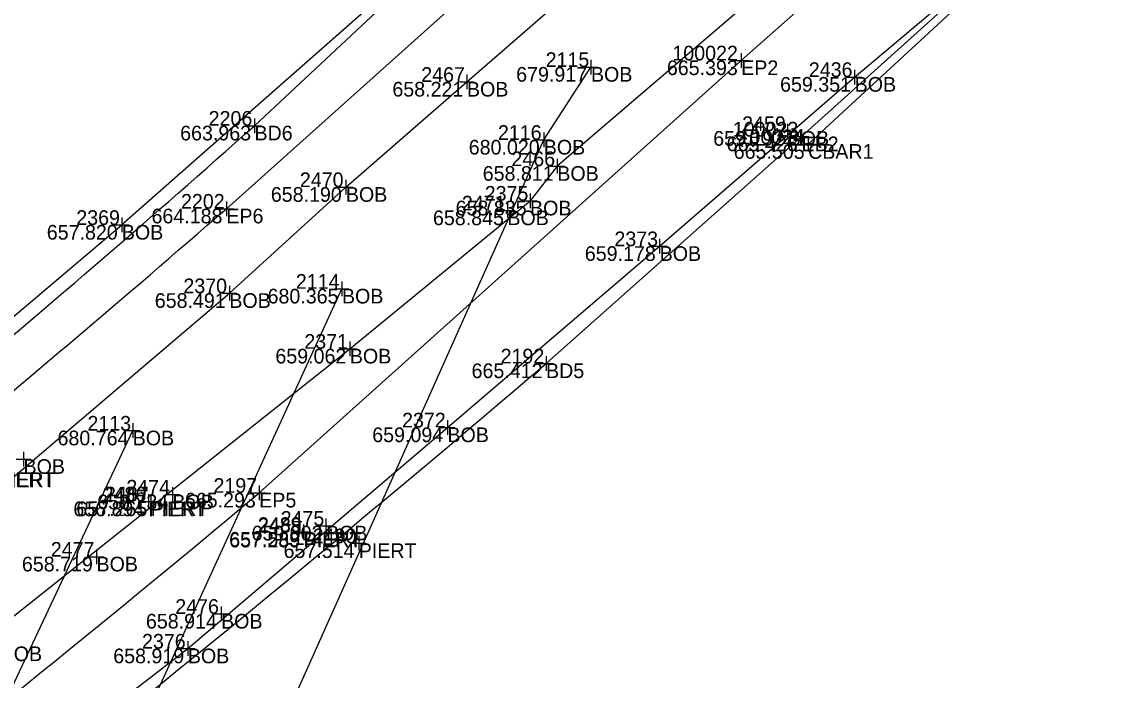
# Model space of a CAD drawing. Extents: x 2197382 to 2204062, y 634117 to 636522.
# Drawn here: x 2202753.9 to 2202828.1, y 635401 to 635445.9 of the extents above; entities that cross this region are included whole.
import ezdxf

# ---------------------------------------------------------------- set-up
doc = ezdxf.new("R2010")
doc.units = 0
for name, color, linetype in [('_CIVIL_CONSTRUCTION', 7, 'Continuous'), ('BR_X_SV_Bottom_of_Beam', 7, 'Continuous'), ('BR_X_SV_Bottom_of_Beam_Text', 7, 'Continuous'), ('BR_X_SV_Deck_Top', 7, 'Continuous'), ('BR_X_SV_Deck_Top_Text', 7, 'Continuous'), ('BR_X_SV_Pier_Cap_Top_Text', 7, 'Continuous'), ('GE_P_Alignment_100_Distances', 7, 'Continuous'), ('GE_X_Alignment', 7, 'Continuous'), ('RD_X_Concrete_Barrier', 7, 'Continuous'), ('SH_Border', 7, 'Continuous'), ('SH_Cut_Line', 7, 'Continuous'), ('SH_Data', 7, 'Continuous')]:
    doc.layers.add(name, color=color, linetype=linetype)

msp = doc.modelspace()

# ---------------------------------------------------------------- linework, layer by layer
at = {"layer": '_CIVIL_CONSTRUCTION'}
for p, q in [((2202802.906, 635443.791), (2202802.906, 635442.791)), ((2202792.169, 635442.844), (2202793.169, 635442.844)), ((2202792.669, 635443.344), (2202792.669, 635442.344)), ((2202792.669, 635442.844), (2202792.669, 635442.844)), ((2202802.406, 635443.291), (2202803.406, 635443.291)), ((2202802.906, 635443.291), (2202802.906, 635443.291)), ((2202784.219, 635442.33), (2202784.219, 635441.33)), ((2202810.139, 635442.162), (2202811.139, 635442.162)), ((2202810.639, 635442.662), (2202810.639, 635441.662)), ((2202810.639, 635442.162), (2202810.639, 635442.162)), ((2202783.719, 635441.83), (2202784.719, 635441.83)), ((2202784.219, 635441.83), (2202784.219, 635441.83)), ((2202769.739, 635439.34), (2202769.739, 635438.34)), ((2202769.239, 635438.84), (2202770.239, 635438.84)), ((2202769.739, 635438.84), (2202769.739, 635438.84)), ((2202789.454, 635438.376), (2202789.454, 635437.376)), ((2202805.573, 635438.476), (2202806.573, 635438.476)), ((2202806.073, 635438.976), (2202806.073, 635437.976)), ((2202806.073, 635438.476), (2202806.073, 635438.476)), ((2202807.016, 635438.602), (2202807.016, 635437.602)), ((2202788.954, 635437.876), (2202789.954, 635437.876)), ((2202789.454, 635437.876), (2202789.454, 635437.876)), ((2202806.516, 635438.102), (2202807.516, 635438.102)), ((2202806.966, 635437.584), (2202807.966, 635437.584)), ((2202807.016, 635438.102), (2202807.016, 635438.102)), ((2202807.466, 635438.084), (2202807.466, 635437.084)), ((2202807.466, 635437.584), (2202807.466, 635437.584)), ((2202789.875, 635436.086), (2202790.875, 635436.086)), ((2202790.375, 635436.586), (2202790.375, 635435.586)), ((2202790.375, 635436.086), (2202790.375, 635436.086)), ((2202775.467, 635434.655), (2202776.467, 635434.655)), ((2202775.967, 635435.155), (2202775.967, 635434.155)), ((2202775.967, 635434.655), (2202775.967, 635434.655)), ((2202788.518, 635434.229), (2202788.518, 635433.229)), ((2202767.323, 635433.185), (2202768.323, 635433.185)), ((2202767.823, 635433.685), (2202767.823, 635432.685)), ((2202767.823, 635433.185), (2202767.823, 635433.185)), ((2202786.973, 635433.561), (2202786.973, 635432.561)), ((2202788.018, 635433.729), (2202789.018, 635433.729)), ((2202788.518, 635433.729), (2202788.518, 635433.729)), ((2202760.7, 635432.577), (2202760.7, 635431.577)), ((2202786.473, 635433.061), (2202787.473, 635433.061)), ((2202786.973, 635433.061), (2202786.973, 635433.061)), ((2202760.2, 635432.077), (2202761.2, 635432.077)), ((2202760.7, 635432.077), (2202760.7, 635432.077)), ((2202797.351, 635431.125), (2202797.351, 635430.125)), ((2202796.851, 635430.625), (2202797.851, 635430.625)), ((2202797.351, 635430.625), (2202797.351, 635430.625)), ((2202768.027, 635427.922), (2202768.027, 635426.922)), ((2202775.701, 635428.223), (2202775.701, 635427.223)), ((2202767.527, 635427.422), (2202768.527, 635427.422)), ((2202768.027, 635427.422), (2202768.027, 635427.422)), ((2202775.201, 635427.723), (2202776.201, 635427.723)), ((2202775.701, 635427.723), (2202775.701, 635427.723)), ((2202775.737, 635423.633), (2202776.737, 635423.633)), ((2202776.237, 635424.133), (2202776.237, 635423.133)), ((2202776.237, 635423.633), (2202776.237, 635423.633)), ((2202789.607, 635423.135), (2202789.607, 635422.135)), ((2202789.107, 635422.635), (2202790.107, 635422.635)), ((2202789.607, 635422.635), (2202789.607, 635422.635)), ((2202761.441, 635418.552), (2202761.441, 635417.552)), ((2202782.387, 635418.269), (2202783.387, 635418.269)), ((2202782.887, 635418.769), (2202782.887, 635417.769)), ((2202782.887, 635418.269), (2202782.887, 635418.269)), ((2202760.941, 635418.052), (2202761.941, 635418.052)), ((2202761.441, 635418.052), (2202761.441, 635418.052)), ((2202753.5, 635416.107), (2202754.5, 635416.107)), ((2202754, 635416.607), (2202754, 635415.607)), ((2202754, 635416.107), (2202754, 635416.107)), ((2202764.147, 635414.193), (2202764.147, 635413.193)), ((2202769.561, 635413.813), (2202770.561, 635413.813)), ((2202770.061, 635414.313), (2202770.061, 635413.313)), ((2202770.061, 635413.813), (2202770.061, 635413.813)), ((2202762.019, 635413.215), (2202763.019, 635413.215)), ((2202762.169, 635413.224), (2202763.169, 635413.224)), ((2202762.519, 635413.715), (2202762.519, 635412.715)), ((2202762.519, 635413.215), (2202762.519, 635413.215)), ((2202762.669, 635413.724), (2202762.669, 635412.724)), ((2202762.669, 635413.224), (2202762.669, 635413.224)), ((2202763.647, 635413.693), (2202764.647, 635413.693)), ((2202764.147, 635413.693), (2202764.147, 635413.693)), ((2202773.076, 635411.645), (2202773.076, 635410.645)), ((2202773.101, 635411.595), (2202773.101, 635410.595)), ((2202774.113, 635411.569), (2202775.113, 635411.569)), ((2202774.613, 635412.069), (2202774.613, 635411.069)), ((2202774.613, 635411.569), (2202774.613, 635411.569)), ((2202772.576, 635411.145), (2202773.576, 635411.145)), ((2202772.601, 635411.095), (2202773.601, 635411.095)), ((2202773.076, 635411.145), (2202773.076, 635411.145)), ((2202773.101, 635411.095), (2202773.101, 635411.095)), ((2202776.844, 635410.872), (2202776.844, 635409.872)), ((2202776.344, 635410.372), (2202777.344, 635410.372)), ((2202776.844, 635410.372), (2202776.844, 635410.372)), ((2202758.475, 635409.456), (2202759.475, 635409.456)), ((2202758.975, 635409.956), (2202758.975, 635408.956)), ((2202758.975, 635409.456), (2202758.975, 635409.456)), ((2202767.464, 635406.063), (2202767.464, 635405.063)), ((2202766.964, 635405.563), (2202767.964, 635405.563)), ((2202767.464, 635405.563), (2202767.464, 635405.563)), ((2202765.2, 635403.692), (2202765.2, 635402.692)), ((2202764.7, 635403.192), (2202765.7, 635403.192)), ((2202765.2, 635403.192), (2202765.2, 635403.192))]:
    msp.add_line(p, q, dxfattribs=at)
at = {"layer": 'BR_X_SV_Bottom_of_Beam'}
for p, q in [((2202789.454, 635437.876), (2202792.669, 635442.844)), ((2202772.072, 635399.002), (2202789.454, 635437.876)), ((2202758.945, 635391.176), (2202775.701, 635427.723)), ((2202745.383, 635383.923), (2202761.441, 635418.052))]:
    msp.add_line(p, q, dxfattribs=at)
for points in [[(2202799.593, 635465.947), (2202791.545, 635459.107), (2202782.041, 635450.982), (2202777.711, 635447.061), (2202760.7, 635432.077)], [(2202768.027, 635427.422), (2202775.967, 635434.655), (2202784.219, 635441.83), (2202796.455, 635452.491), (2202804.428, 635459.062), (2202811.432, 635465.056)], [(2202821.428, 635462.569), (2202813.764, 635456.102), (2202803.94, 635447.733), (2202790.375, 635436.086), (2202788.518, 635433.729)], [(2202550.738, 635261.3), (2202572.992, 635273.891), (2202594.556, 635285.879), (2202604.099, 635291.315), (2202615.232, 635297.565), (2202632.636, 635308.407), (2202649.916, 635319.32), (2202686.545, 635342.9), (2202715.55, 635365.054), (2202734.551, 635379.543), (2202765.2, 635403.192), (2202782.887, 635418.269), (2202797.351, 635430.625), (2202810.639, 635442.162), (2202822.488, 635452.15)], [(2202692.151, 635358.452), (2202706.563, 635369.157), (2202730.439, 635387.213), (2202776.237, 635423.633), (2202788.518, 635433.729)], [(2202513.324, 635270.745), (2202518.461, 635273.222), (2202532.26, 635280.283), (2202548.237, 635288.645), (2202560.651, 635295.117), (2202588.283, 635310.399), (2202608.693, 635322.992), (2202620.515, 635330.213), (2202626.072, 635333.707), (2202636.254, 635340.133), (2202656.933, 635353.888), (2202662.455, 635358.969), (2202720.902, 635399.769), (2202735.154, 635410.438), (2202760.7, 635432.077)], [(2202624.848, 635323.108), (2202626.632, 635325.163), (2202640.898, 635333.252), (2202660.713, 635346.321), (2202681.445, 635361.418), (2202700.993, 635375.17), (2202725.622, 635393.015), (2202741.163, 635404.571), (2202768.027, 635427.422)]]:
    msp.add_lwpolyline(points, dxfattribs=at)
at = {"layer": 'BR_X_SV_Deck_Top'}
for p, q in [((2202769.739, 635438.84), (2202791.176, 635458.867)), ((2202789.607, 635422.635), (2202807.016, 635438.102))]:
    msp.add_line(p, q, dxfattribs=at)
for points in [[(2202430.051, 635233.588), (2202439.74, 635238.507), (2202466.339, 635247.691), (2202507.168, 635268.028), (2202543.723, 635286.397), (2202574.877, 635303.715), (2202604.911, 635320.157), (2202634.127, 635339.4), (2202663.018, 635358.594), (2202692.445, 635376.507), (2202729.246, 635404.451), (2202755.806, 635426.417), (2202769.739, 635438.84)], [(2202458.051, 635216.681), (2202477.116, 635219.979), (2202511.723, 635243.78), (2202554.955, 635262.299), (2202588.014, 635280.674), (2202608.342, 635292.387), (2202640.833, 635312.137), (2202668.147, 635329.948), (2202698.573, 635351.315), (2202722.135, 635368.649), (2202754.604, 635393.426), (2202777.494, 635412.293), (2202789.607, 635422.635)]]:
    msp.add_open_spline(points, degree=3, dxfattribs=at)
at = {"layer": 'GE_P_Alignment_100_Distances'}
for p, q in [((2202767.823, 635433.185), (2202793.579, 635456.25)), ((2202770.061, 635413.813), (2202802.906, 635443.291))]:
    msp.add_line(p, q, dxfattribs=at)
msp.add_lwpolyline([(2202838.828, 635477.544), (2202824.168, 635462.1), (2202802.906, 635443.291)], dxfattribs=at)
for points in [[(2202483.163, 635252.761), (2202495.402, 635258.227), (2202515.209, 635267.824), (2202539.505, 635280.183), (2202556.272, 635289.074), (2202570.794, 635297.089), (2202585.76, 635305.335), (2202607.83, 635319.01), (2202630.778, 635332.646), (2202656.431, 635348.815), (2202675.69, 635362.468), (2202698.981, 635379.185), (2202729.904, 635401.353), (2202753.674, 635420.874), (2202767.823, 635433.185)], [(2202457.668, 635223.282), (2202466.48, 635226.872), (2202500.455, 635242.355), (2202539.476, 635261.183), (2202573.06, 635279.52), (2202585.609, 635286.631), (2202599.84, 635294.842), (2202617.618, 635305.231), (2202642.294, 635320.395), (2202667.372, 635336.77), (2202691.723, 635353.633), (2202713.413, 635369.403), (2202739.641, 635388.973), (2202758.657, 635404.276), (2202770.061, 635413.813)]]:
    msp.add_open_spline(points, degree=3, dxfattribs=at)
at = {"layer": 'GE_X_Alignment'}
msp.add_lwpolyline([(2202845.854, 635473.172), (2202828.699, 635457.658), (2202807.016, 635438.102)], dxfattribs=at)
at = {"layer": 'RD_X_Concrete_Barrier'}
msp.add_lwpolyline([(2202849.035, 635475.414), (2202828.969, 635457.445), (2202807.466, 635437.584)], dxfattribs=at)

# ---------------------------------------------------------------- texts
at = {"layer": 'BR_X_SV_Bottom_of_Beam_Text'}
for s, p in [('2115', (2202789.58, 635442.844)), ('2467', (2202781.104, 635441.83)), ('679.917', (2202787.573, 635441.844)), ('BOB', (2202792.669, 635441.844)), ('2436', (2202807.516, 635442.162)), ('659.351', (2202805.557, 635441.162)), ('BOB', (2202810.639, 635441.162)), ('658.221', (2202779.137, 635440.83)), ('BOB', (2202784.219, 635440.83)), ('2459', (2202802.971, 635438.476)), ('2116', (2202786.331, 635437.876)), ('659.192', (2202801, 635437.476)), ('BOB', (2202806.073, 635437.476)), ('680.020', (2202784.34, 635436.876)), ('BOB', (2202789.454, 635436.876)), ('2466', (2202787.252, 635436.086)), ('658.811', (2202785.293, 635435.086)), ('BOB', (2202790.375, 635435.086)), ('2470', (2202772.835, 635434.655)), ('658.190', (2202770.853, 635433.655)), ('BOB', (2202775.967, 635433.655)), ('2375', (2202785.429, 635433.729)), ('2471', (2202783.873, 635433.061)), ('2369', (2202757.598, 635432.077)), ('658.845', (2202781.903, 635432.061)), ('658.835', (2202783.448, 635432.729)), ('BOB', (2202786.973, 635432.061)), ('BOB', (2202788.518, 635432.729)), ('657.820', (2202755.586, 635431.077)), ('BOB', (2202760.7, 635431.077)), ('2373', (2202794.268, 635430.625)), ('659.178', (2202792.251, 635429.625)), ('BOB', (2202797.351, 635429.625)), ('2114', (2202772.56, 635427.723)), ('2370', (2202764.895, 635427.422)), ('658.491', (2202762.945, 635426.422)), ('BOB', (2202768.027, 635426.422)), ('680.365', (2202770.631, 635426.723)), ('BOB', (2202775.701, 635426.723)), ('2371', (2202773.137, 635423.633)), ('659.062', (2202771.164, 635422.633)), ('BOB', (2202776.237, 635422.633)), ('2113', (2202758.358, 635418.052)), ('2372', (2202779.795, 635418.269)), ('659.094', (2202777.765, 635417.269)), ('BOB', (2202782.887, 635417.269)), ('680.764', (2202756.319, 635417.052)), ('BOB', (2202761.441, 635417.052)), ('BOB', (2202754, 635415.107)), ('2474', (2202761.006, 635413.693)), ('658.734', (2202759.025, 635412.693)), ('BOB', (2202764.147, 635412.693)), ('2475', (2202771.524, 635411.569)), ('659.002', (2202769.54, 635410.569)), ('BOB', (2202774.613, 635410.569)), ('2477', (2202755.86, 635409.456)), ('658.719', (2202753.891, 635408.456)), ('BOB', (2202758.975, 635408.456)), ('2476', (2202764.341, 635405.563)), ('658.914', (2202762.342, 635404.563)), ('BOB', (2202767.464, 635404.563)), ('2376', (2202762.077, 635403.192)), ('BOB', (2202752.443, 635402.339)), ('658.919', (2202760.116, 635402.192)), ('BOB', (2202765.2, 635402.192))]:
    msp.add_text(s, height=1, dxfattribs=at).set_placement(p)
at = {"layer": 'BR_X_SV_Deck_Top_Text'}
for s, p in [('2206', (2202766.616, 635438.84)), ('663.963', (2202764.675, 635437.84)), ('BD6', (2202769.739, 635437.84)), ('2192', (2202786.515, 635422.635)), ('665.412', (2202784.534, 635421.635)), ('BD5', (2202789.607, 635421.635))]:
    msp.add_text(s, height=1, dxfattribs=at).set_placement(p)
at = {"layer": 'BR_X_SV_Pier_Cap_Top_Text'}
for s, p in [('PIERT', (2202752.185, 635414.215)), ('PIERT', (2202752.248, 635414.198)), ('2486', (2202759.396, 635413.215)), ('2487', (2202759.554, 635413.224)), ('656.894', (2202757.397, 635412.215)), ('657.265', (2202757.599, 635412.224)), ('PIERT', (2202762.519, 635412.215)), ('PIERT', (2202762.669, 635412.224)), ('2489', (2202769.974, 635411.145)), ('2488', (2202769.982, 635411.095)), ('657.533', (2202768.012, 635410.145)), ('657.289', (2202768.017, 635410.095)), ('PIERT', (2202773.076, 635410.145)), ('PIERT', (2202773.101, 635410.095)), ('2490', (2202773.712, 635410.372)), ('657.514', (2202771.722, 635409.372)), ('PIERT', (2202776.844, 635409.372))]:
    msp.add_text(s, height=1, dxfattribs=at).set_placement(p)
at = {"layer": 'SH_Border'}
for s, p in [('EP2', (2202802.906, 635442.291)), ('EB2', (2202807.016, 635437.102)), ('CBAR1', (2202807.466, 635436.584)), ('EP6', (2202767.823, 635432.185)), ('EP5', (2202770.061, 635412.813))]:
    msp.add_text(s, height=1, dxfattribs=at).set_placement(p)
at = {"layer": 'SH_Cut_Line'}
for s, p in [('100022', (2202798.218, 635443.291)), ('100023', (2202802.337, 635438.102)), ('100024', (2202802.729, 635437.584)), ('2202', (2202764.731, 635433.185)), ('2197', (2202766.946, 635413.813))]:
    msp.add_text(s, height=1, dxfattribs=at).set_placement(p)
at = {"layer": 'SH_Data'}
for s, p in [('665.393', (2202797.842, 635442.291)), ('665.426', (2202801.912, 635437.102)), ('665.505', (2202802.396, 635436.584)), ('664.188', (2202762.723, 635432.185)), ('665.293', (2202764.997, 635412.813))]:
    msp.add_text(s, height=1, dxfattribs=at).set_placement(p)

doc.saveas('drawing.dxf')
